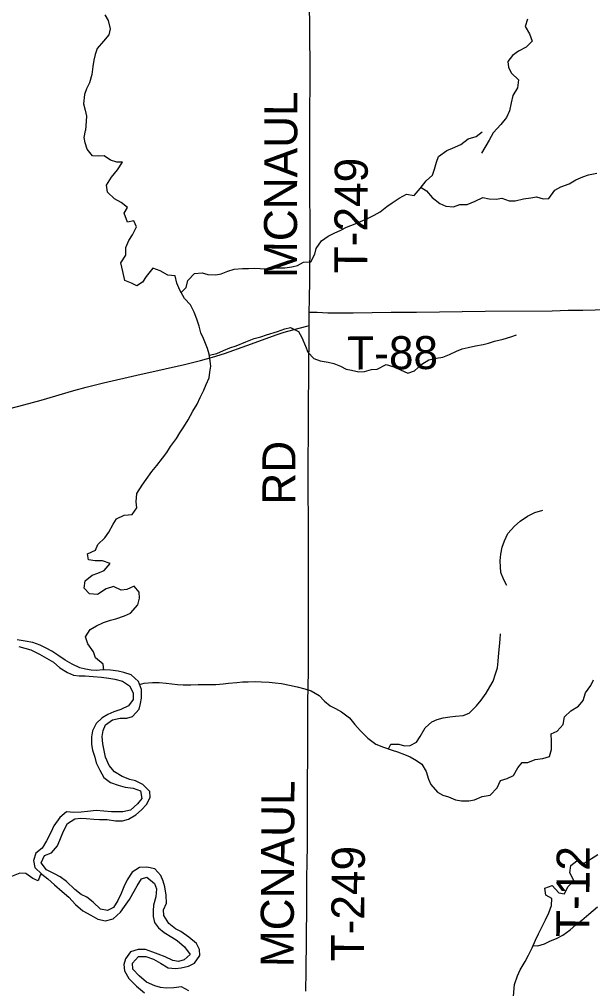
# Model space of a CAD drawing. Extents: x 0 to 34, y 0 to 22.
# Drawn here: x 6.497 to 7.484, y 14.926 to 16.591 of the extents above; entities that cross this region are included whole.
import ezdxf

# ---------------------------------------------------------------- set-up
doc = ezdxf.new("R2010")
doc.units = 0
for name, color, linetype in [('GM_X_Major_River', 7, 'Continuous'), ('GM_X_Minor_Lake', 7, 'Continuous'), ('GM_X_Minor_River', 7, 'Continuous'), ('GM_X_Township_Road', 7, 'Continuous'), ('GM_X_Township_Road_Text', 7, 'Continuous')]:
    doc.layers.add(name, color=color, linetype=linetype)

msp = doc.modelspace()

# ---------------------------------------------------------------- linework, layer by layer
at = {"layer": 'GM_X_Major_River'}
for points in [[(6.5929, 15.2176), (6.6024, 15.2184), (6.6126, 15.218), (6.6255, 15.2172), (6.6354, 15.2165), (6.6486, 15.2161), (6.6627, 15.2142), (6.6748, 15.2142), (6.685, 15.2169), (6.6979, 15.2245), (6.7078, 15.2328), (6.7161, 15.2423), (6.7226, 15.254), (6.7218, 15.2643), (6.7101, 15.2764), (6.6972, 15.2829), (6.6873, 15.2851), (6.6741, 15.2901), (6.6612, 15.298), (6.6517, 15.309), (6.6457, 15.3234), (6.6434, 15.3352), (6.6411, 15.3466), (6.64, 15.3587), (6.6415, 15.369), (6.6457, 15.3788), (6.6578, 15.3875), (6.6707, 15.3906), (6.6821, 15.3902), (6.6919, 15.3932), (6.7033, 15.4058), (6.706, 15.4156), (6.7075, 15.4251), (6.7075, 15.4395), (6.7022, 15.4535), (6.6897, 15.4649), (6.6772, 15.4691), (6.6677, 15.4714), (6.6541, 15.4729), (6.6408, 15.4733), (6.6302, 15.4725), (6.6207, 15.4729), (6.6112, 15.4744), (6.6014, 15.4771), (6.5885, 15.4831), (6.5764, 15.4903), (6.5635, 15.4987), (6.5532, 15.5055), (6.5438, 15.5108), (6.5335, 15.5157), (6.5207, 15.5207), (6.5074, 15.5229), (6.4937, 15.5252)], [(6.4968, 15.5135), (6.507, 15.5108), (6.5172, 15.5078), (6.532, 15.5006), (6.5441, 15.4937), (6.5559, 15.4865), (6.5673, 15.4771), (6.5801, 15.4691), (6.5904, 15.4642), (6.6006, 15.4634), (6.6108, 15.463), (6.6245, 15.4619), (6.6389, 15.4607), (6.6514, 15.4592), (6.6616, 15.4577), (6.6749, 15.4539), (6.687, 15.4463), (6.6935, 15.4342), (6.6935, 15.4228), (6.6851, 15.4114), (6.6722, 15.4054), (6.6597, 15.4016), (6.6495, 15.3966), (6.64, 15.391), (6.6298, 15.3815), (6.6233, 15.3686), (6.6218, 15.3583), (6.6218, 15.3451), (6.6233, 15.3356), (6.6271, 15.3234), (6.6297, 15.314), (6.6358, 15.3014), (6.6426, 15.2886), (6.6543, 15.2802), (6.6672, 15.2753), (6.6794, 15.2719), (6.693, 15.27), (6.7059, 15.2654), (6.7082, 15.2525), (6.7006, 15.243), (6.6888, 15.2324), (6.6756, 15.2298), (6.6661, 15.2294), (6.6562, 15.2294), (6.643, 15.2309), (6.6293, 15.2317), (6.6149, 15.2301), (6.6035, 15.229), (6.591, 15.2286), (6.5785, 15.2298), (6.5671, 15.2195)], [(6.5671, 15.2195), (6.5569, 15.2055), (6.5519, 15.1949), (6.5444, 15.1797), (6.5364, 15.1672), (6.5258, 15.1584), (6.5216, 15.1459), (6.5239, 15.1338), (6.536, 15.1224), (6.5462, 15.1144), (6.558, 15.1038), (6.5712, 15.0924), (6.5826, 15.0826), (6.594, 15.0705), (6.6065, 15.0595), (6.6205, 15.0519), (6.6326, 15.045), (6.6455, 15.042), (6.6588, 15.0454), (6.6713, 15.0572), (6.6785, 15.0667), (6.6872, 15.0788), (6.6929, 15.0894), (6.7001, 15.1023), (6.7073, 15.1141), (6.7168, 15.1171), (6.7297, 15.1065), (6.7331, 15.097), (6.732, 15.0837), (6.7282, 15.0689), (6.7274, 15.0595), (6.7274, 15.0496), (6.73, 15.0394), (6.7369, 15.0299), (6.7467, 15.0219), (6.7596, 15.014), (6.7691, 15.0083), (6.7816, 14.9973), (6.7911, 14.9844), (6.7808, 14.9753), (6.7713, 14.9726), (6.7615, 14.9741), (6.7482, 14.9802), (6.7365, 14.9847), (6.727, 14.9885), (6.7145, 14.9927), (6.7016, 14.9931), (6.6887, 14.9889), (6.68, 14.9768), (6.6769, 14.9669), (6.6784, 14.9563), (6.686, 14.943), (6.6989, 14.9301), (6.7129, 14.9187)], [(6.7891, 14.9218), (6.7766, 14.9286), (6.7633, 14.9271), (6.7501, 14.9267), (6.7402, 14.9278), (6.7304, 14.9305), (6.7163, 14.937), (6.7035, 14.9476), (6.6925, 14.9593), (6.6921, 14.9692), (6.7023, 14.9809), (6.7152, 14.9809), (6.7281, 14.9764), (6.7402, 14.9696), (6.7535, 14.9612), (6.766, 14.9601), (6.7759, 14.9616), (6.7884, 14.9643), (6.7986, 14.9692), (6.8077, 14.9829), (6.8074, 14.9927), (6.8021, 15.0033), (6.7892, 15.0143), (6.7755, 15.0238), (6.7661, 15.0287), (6.7543, 15.0375), (6.746, 15.0515), (6.7452, 15.061), (6.7505, 15.0727), (6.7502, 15.0864), (6.7475, 15.1008), (6.7449, 15.1103), (6.7411, 15.1202), (6.7305, 15.1315), (6.7168, 15.1346), (6.7043, 15.1338), (6.6914, 15.1258), (6.6831, 15.1129), (6.6774, 15.1004), (6.6728, 15.0894), (6.6671, 15.0769), (6.6595, 15.0651), (6.6489, 15.0602), (6.6368, 15.0625), (6.6247, 15.0742), (6.6133, 15.0826), (6.6038, 15.0875), (6.5928, 15.0959), (6.5784, 15.1099), (6.5678, 15.1179), (6.558, 15.1228), (6.5443, 15.13), (6.5352, 15.1421), (6.5405, 15.1546), (6.5527, 15.1588), (6.5633, 15.1713), (6.5694, 15.1865), (6.5732, 15.1964), (6.58, 15.2093), (6.5929, 15.2176)]]:
    msp.add_lwpolyline(points, dxfattribs=at)
at = {"layer": 'GM_X_Minor_Lake'}
msp.add_lwpolyline([(7.3716, 16.5918), (7.3677, 16.5793), (7.3752, 16.5664), (7.3797, 16.5538), (7.3691, 16.5436), (7.3561, 16.5365), (7.3458, 16.5293), (7.3378, 16.5191), (7.3389, 16.5089), (7.3434, 16.4993), (7.3563, 16.4875), (7.3543, 16.4735), (7.3466, 16.4602), (7.3436, 16.4481), (7.3408, 16.4344), (7.3355, 16.4227), (7.3259, 16.4106), (7.3125, 16.3964), (7.3055, 16.3836), (7.2924, 16.3612)], dxfattribs=at)
at = {"layer": 'GM_X_Minor_River'}
for points in [[(6.6446, 16.5992), (6.6502, 16.5893), (6.6536, 16.5749), (6.6512, 16.5646), (6.6424, 16.5537), (6.6314, 16.5412), (6.6279, 16.531), (6.6256, 16.5211), (6.624, 16.5101), (6.6224, 16.4968), (6.6182, 16.4824), (6.6128, 16.4722), (6.6094, 16.462), (6.6078, 16.446), (6.6104, 16.4354), (6.613, 16.4251), (6.611, 16.4003)], [(6.6663, 16.3328), (6.675, 16.346), (6.6652, 16.346), (6.6542, 16.3495), (6.6432, 16.3567), (6.6329, 16.3563), (6.6235, 16.3567), (6.614, 16.3684), (6.6106, 16.379), (6.6087, 16.3885), (6.611, 16.4003)], [(6.7757, 16.1222), (6.7845, 16.1306), (6.7875, 16.1427), (6.7985, 16.1545), (6.8121, 16.1556), (6.8216, 16.153), (6.8353, 16.1522), (6.8448, 16.1541), (6.8561, 16.1587), (6.8671, 16.1621), (6.8815, 16.1632), (6.8914, 16.1632), (6.902, 16.1636), (6.9115, 16.1632), (6.9232, 16.1629), (6.9335, 16.1636), (6.9441, 16.1644), (6.9543, 16.1644), (6.9661, 16.1659), (6.9759, 16.1686), (6.9862, 16.1739), (6.9987, 16.1746), (7.0059, 16.1879), (7.0082, 16.1974), (7.0173, 16.2107), (7.0287, 16.2186), (7.0389, 16.2239), (7.0503, 16.2292), (7.0605, 16.2342), (7.0749, 16.2399), (7.0886, 16.2459), (7.0984, 16.2505), (7.1079, 16.2547), (7.1181, 16.2607), (7.1295, 16.2698), (7.139, 16.2763), (7.1508, 16.2839), (7.1636, 16.2911), (7.1769, 16.2888), (7.1872, 16.3006), (7.1974, 16.3138), (7.2084, 16.3233), (7.2118, 16.334), (7.2152, 16.3461), (7.2183, 16.3556), (7.2327, 16.3658), (7.2425, 16.37), (7.2569, 16.3764), (7.2698, 16.3859), (7.2831, 16.3901), (7.2934, 16.3981)], [(6.6429, 15.4732), (6.6419, 15.4831), (6.6287, 15.4941), (6.6249, 15.5047), (6.615, 15.518), (6.6113, 15.5305), (6.6192, 15.5427), (6.6299, 15.5491), (6.642, 15.5548), (6.6541, 15.5586), (6.6636, 15.5609), (6.6784, 15.5662), (6.6886, 15.5711), (6.7011, 15.5855), (6.7042, 15.5965), (6.7038, 15.6072), (6.6951, 15.6174), (6.6822, 15.6117), (6.6727, 15.6102), (6.6595, 15.6166), (6.6466, 15.6125), (6.6318, 15.603), (6.6181, 15.6041), (6.6087, 15.614), (6.6106, 15.6265), (6.6227, 15.636), (6.6322, 15.6398), (6.6432, 15.6443), (6.6534, 15.6561), (6.6405, 15.6606), (6.628, 15.6606), (6.6163, 15.6625), (6.6144, 15.6728), (6.6284, 15.6792), (6.6326, 15.6887), (6.6447, 15.7005), (6.6515, 15.7103), (6.6591, 15.7236), (6.6648, 15.7331), (6.6777, 15.7392), (6.6914, 15.7403), (6.6993, 15.7521), (6.6986, 15.7623), (6.6993, 15.7763), (6.7085, 15.7911), (6.7157, 15.8006), (6.7255, 15.8146), (6.7339, 15.8245), (6.7437, 15.837), (6.7509, 15.8469), (6.7574, 15.8571), (6.7676, 15.8708), (6.7733, 15.8806), (6.7802, 15.8913), (6.7878, 15.9034), (6.7961, 15.9182), (6.8033, 15.9303), (6.8086, 15.9413), (6.8147, 15.9539), (6.8189, 15.9641), (6.8238, 15.9755), (6.8253, 15.985), (6.8268, 15.9952), (6.8257, 16.0047), (6.8238, 16.0161), (6.8212, 16.0259), (6.814, 16.043), (6.8098, 16.0528), (6.8068, 16.0642), (6.803, 16.076), (6.7981, 16.0881), (6.792, 16.1006), (6.7818, 16.1116), (6.7735, 16.1261), (6.7685, 16.1382), (6.7655, 16.1507), (6.7526, 16.1515), (6.7397, 16.159), (6.7272, 16.1636), (6.7158, 16.1492), (6.7094, 16.1397), (6.6995, 16.1333), (6.6901, 16.1378), (6.6787, 16.1427), (6.6753, 16.1579), (6.6719, 16.1727), (6.6806, 16.186), (6.6806, 16.1992), (6.6859, 16.2114), (6.692, 16.2209), (6.6988, 16.2349), (6.6943, 16.2451), (6.6833, 16.2429), (6.678, 16.2584), (6.6833, 16.2679), (6.6723, 16.2766), (6.661, 16.2827), (6.6488, 16.2941), (6.6473, 16.3066), (6.656, 16.3199), (6.6663, 16.3328)], [(7.1885, 16.3023), (7.1978, 16.2968), (7.2076, 16.285), (7.2205, 16.2748), (7.2311, 16.2702), (7.2444, 16.2691), (7.2554, 16.2729), (7.2679, 16.2733), (7.2815, 16.279), (7.2948, 16.2854), (7.3058, 16.2831), (7.3176, 16.2824), (7.3274, 16.2839), (7.3403, 16.2797), (7.3502, 16.2797), (7.3646, 16.2831), (7.3771, 16.2847), (7.3869, 16.2862), (7.3983, 16.2828), (7.4082, 16.2835), (7.4184, 16.2976), (7.429, 16.3033), (7.4434, 16.3089), (7.4548, 16.3158), (7.4666, 16.3207), (7.4764, 16.3241), (7.4908, 16.3268)], [(6.8242, 16.014), (6.8371, 16.0172), (6.8485, 16.0225), (6.8598, 16.0267), (6.8705, 16.0305), (6.8871, 16.0373), (6.9016, 16.043), (6.9129, 16.046), (6.9228, 16.0491), (6.9417, 16.0551), (6.9543, 16.0593), (6.9641, 16.0616), (6.9774, 16.0548), (6.9834, 16.0445), (6.9899, 16.0297), (6.9937, 16.0195), (7.0043, 16.0085), (7.0149, 16.0043), (7.0285, 16.002), (7.0384, 15.9998), (7.0498, 15.9956), (7.0596, 15.9903), (7.0691, 15.9884), (7.0816, 15.9857), (7.0911, 15.9861), (7.1032, 15.9895), (7.1131, 15.9903), (7.1282, 15.9983), (7.1419, 15.9941), (7.1529, 15.9888), (7.1658, 15.9831), (7.1771, 15.9873), (7.1896, 15.999), (7.2018, 16.0062), (7.2151, 16.0089), (7.2257, 16.0108), (7.2374, 16.0153), (7.2496, 16.0214), (7.259, 16.0252), (7.2697, 16.0275), (7.2822, 16.0301), (7.2951, 16.0328), (7.3045, 16.0351), (7.3151, 16.0381), (7.3296, 16.0419), (7.3428, 16.0457), (7.3527, 16.0491)], [(7.3362, 15.6182), (7.3308, 15.6281), (7.3259, 15.641), (7.3252, 15.6505), (7.3248, 15.6611), (7.3259, 15.6725), (7.3282, 15.6842), (7.332, 15.6952), (7.3377, 15.7077), (7.3495, 15.7203), (7.359, 15.729), (7.3715, 15.7377), (7.3844, 15.7438), (7.398, 15.748)], [(7.1325, 15.3378), (7.1366, 15.3459), (7.1503, 15.3459), (7.1601, 15.3432), (7.17, 15.3436), (7.1806, 15.3493), (7.187, 15.3591), (7.1958, 15.3736), (7.2068, 15.3842), (7.2162, 15.388), (7.2265, 15.391), (7.2382, 15.3929), (7.2477, 15.3941), (7.261, 15.3948), (7.2712, 15.399), (7.2837, 15.4115), (7.2917, 15.4214), (7.3004, 15.4335), (7.3069, 15.4441), (7.3126, 15.454), (7.3167, 15.4665), (7.3198, 15.4767), (7.3213, 15.4885), (7.3224, 15.5029), (7.3232, 15.5139), (7.3243, 15.5261), (7.3251, 15.5355)], [(6.7043, 15.4481), (6.7124, 15.4505), (6.7265, 15.4517), (6.7378, 15.4517), (6.75, 15.4509), (6.7595, 15.4494), (6.7693, 15.4482), (6.7795, 15.4475), (6.7924, 15.4475), (6.8053, 15.4482), (6.8152, 15.4486), (6.8353, 15.4486), (6.8478, 15.4494), (6.8573, 15.4505), (6.8713, 15.452), (6.8815, 15.4528), (6.891, 15.4532), (6.9039, 15.4536), (6.9141, 15.4532), (6.9274, 15.4524), (6.9373, 15.4513), (6.9486, 15.4498), (6.9623, 15.4471), (6.9755, 15.4445), (6.9884, 15.4411), (6.9994, 15.4373), (7.0131, 15.4293), (7.0222, 15.4198), (7.032, 15.4115), (7.0415, 15.4073), (7.0517, 15.4016), (7.0654, 15.391), (7.0745, 15.3796), (7.0839, 15.3694), (7.0968, 15.3561), (7.1108, 15.3459), (7.1237, 15.3409), (7.1385, 15.3356), (7.148, 15.3326), (7.1601, 15.328), (7.17, 15.3239), (7.1806, 15.3178), (7.19, 15.3114), (7.1972, 15.2988), (7.2014, 15.2859), (7.2052, 15.2765), (7.2165, 15.2632), (7.226, 15.2583), (7.2355, 15.2552), (7.2476, 15.2503), (7.2579, 15.2484), (7.2707, 15.2484), (7.2802, 15.2503), (7.2935, 15.256), (7.3075, 15.2583), (7.3193, 15.2708), (7.325, 15.2833), (7.3367, 15.2867), (7.3477, 15.2917), (7.3549, 15.3049), (7.3625, 15.3144), (7.372, 15.3144), (7.3849, 15.3193), (7.3978, 15.3212), (7.4095, 15.3247), (7.413, 15.3364), (7.4126, 15.3508), (7.4122, 15.3637), (7.4224, 15.3683), (7.4331, 15.3797), (7.435, 15.3929), (7.446, 15.4028), (7.4596, 15.4111), (7.4676, 15.421), (7.4714, 15.4339), (7.4805, 15.4464), (7.485, 15.4563)], [(7.3475, 14.9127), (7.3494, 14.9328), (7.3544, 14.9476), (7.3589, 14.9579), (7.3673, 14.9723), (7.3733, 14.9833), (7.3794, 14.9958), (7.3851, 15.0091), (7.3904, 15.0201), (7.3965, 15.0311), (7.4026, 15.044), (7.4083, 15.0557), (7.4128, 15.0686), (7.4132, 15.0804), (7.4033, 15.0865), (7.4015, 15.0986), (7.414, 15.1028), (7.4257, 15.0903), (7.4352, 15.0884), (7.4409, 15.1005), (7.4511, 15.1115), (7.4443, 15.1248), (7.4462, 15.1373), (7.4564, 15.1456), (7.4693, 15.1411), (7.4927, 15.1562)], [(6.5351, 15.1232), (6.5333, 15.1209), (6.5299, 15.111), (6.5204, 15.1152), (6.5087, 15.1235), (6.4985, 15.1243), (6.484, 15.1186)], [(7.3813, 15.0001), (7.3896, 14.9992), (7.4006, 15.0026), (7.4113, 15.0076), (7.4215, 15.0121), (7.4321, 15.0174), (7.445, 15.0269), (7.4545, 15.0353), (7.4651, 15.0436), (7.4772, 15.0538), (7.492, 15.0664)]]:
    msp.add_lwpolyline(points, dxfattribs=at)
at = {"layer": 'GM_X_Township_Road'}
for points in [[(6.9962, 16.0884), (6.9965, 16.1097), (6.9969, 16.1439), (6.9975, 16.2122), (6.9977, 16.2494), (6.9973, 16.2835), (6.997, 16.3394), (6.997, 16.3798), (6.9971, 16.4077), (6.9976, 16.5072), (6.9968, 16.6284)], [(6.9962, 16.0884), (7.0036, 16.0881), (7.0097, 16.0879), (7.0283, 16.0873), (7.0718, 16.0872), (7.1371, 16.0882), (7.1807, 16.0884), (7.2989, 16.0896), (7.4138, 16.0907), (7.4417, 16.0914), (7.4665, 16.0918), (7.4881, 16.0924), (7.5004, 16.0927), (7.5058, 16.0927)], [(6.9958, 16.065), (6.9959, 16.0724), (6.9962, 16.0884)], [(6.4298, 15.9095), (6.5049, 15.9289), (6.5349, 15.9371), (6.5914, 15.9535), (6.6123, 15.9593), (6.6423, 15.9666), (6.6998, 15.9798), (6.7483, 15.9906), (6.7817, 15.9981), (6.8088, 16.0049), (6.8298, 16.0108), (6.8505, 16.0174), (6.8886, 16.0308), (6.9411, 16.0499), (6.9529, 16.0537), (6.9678, 16.058), (6.9918, 16.064), (6.9958, 16.065)], [(6.9904, 14.9215), (6.9907, 14.9557), (6.9919, 15.0675), (6.9918, 15.1015), (6.992, 15.1138), (6.9924, 15.1448), (6.993, 15.1696), (6.9929, 15.1883), (6.9931, 15.2566), (6.9932, 15.2846), (6.9935, 15.3219), (6.9936, 15.3623), (6.9939, 15.4182), (6.9946, 15.471), (6.9948, 15.5051), (6.9951, 15.5722), (6.9951, 15.6281), (6.9951, 15.7183), (6.9945, 15.7928), (6.9945, 15.8238), (6.9947, 15.8889), (6.9947, 15.9218), (6.9953, 15.9881), (6.9958, 16.0507), (6.9958, 16.065)]]:
    msp.add_lwpolyline(points, dxfattribs=at)

# ---------------------------------------------------------------- texts
at = {"layer": 'GM_X_Township_Road_Text'}
for s, rotation, p in [('MCNAUL', 89.8418, (6.9749, 16.1467)), ('T-249', 89.7194, (7.0959, 16.1548)), ('T-88', 0.3544, (7.0616, 15.9895)), ('RD', 90, (6.9724, 15.7573)), ('MCNAUL', 89.6839, (6.9691, 14.9625)), ('T-249', 89.4391, (7.0901, 14.9722)), ('T-12', 89.6355, (7.4777, 15.0142))]:
    msp.add_text(s, height=0.05682, rotation=rotation, dxfattribs=at).set_placement(p)

doc.saveas('drawing.dxf')
